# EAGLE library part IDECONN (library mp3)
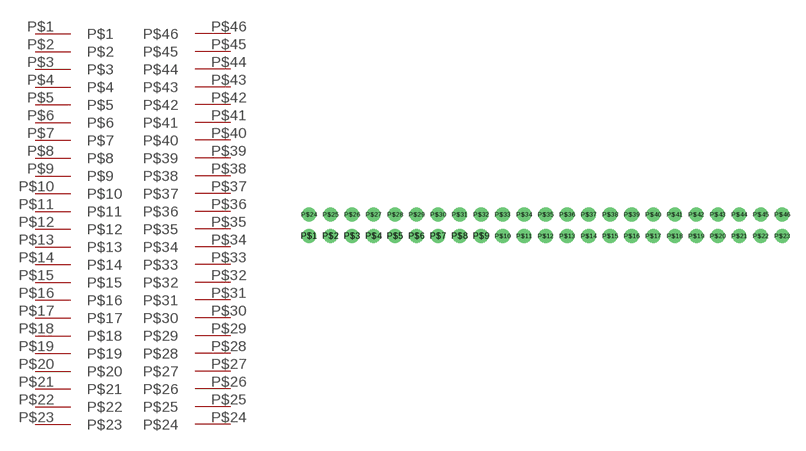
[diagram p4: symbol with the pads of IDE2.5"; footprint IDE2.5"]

Designator prefix -

## IDECONN  [IDE2.5"]
P$1  P$1
P$2  P$2
P$3  P$3
P$4  P$4
P$5  P$5
P$6  P$6
P$7  P$7
P$8  P$8
P$9  P$9
P$10  P$10
P$11  P$11
P$12  P$12
P$13  P$13
P$14  P$14
P$15  P$15
P$16  P$16
P$17  P$17
P$18  P$18
P$19  P$19
P$20  P$20
P$21  P$21
P$22  P$22
P$23  P$23
P$24  P$24
P$25  P$25
P$26  P$26
P$27  P$27
P$28  P$28
P$29  P$29
P$30  P$30
P$31  P$31
P$32  P$32
P$33  P$33
P$34  P$34
P$35  P$35
P$36  P$36
P$37  P$37
P$38  P$38
P$39  P$39
P$40  P$40
P$41  P$41
P$42  P$42
P$43  P$43
P$44  P$44
P$45  P$45
P$46  P$46

## Footprint IDE2.5" (pad centres in mm)
drill 0.813 round: P$1 -20,0; P$2 -18,0; P$3 -16,0; P$4 -14,0; P$5 -12,0; P$6 -10,0; P$7 -8,0; P$8 -6,0; P$9 -4,0; P$10 -2,0; P$11 0,0; P$12 2,0; P$13 4,0; P$14 6,0; P$15 8,0; P$16 10,0; P$17 12,0; P$18 14,0; P$19 16,0; P$20 18,0; P$21 20,0; P$22 22,0; P$23 24,0; P$24 -20,2; P$25 -18,2; P$26 -16,2; P$27 -14,2; P$28 -12,2; P$29 -10,2; P$30 -8,2; P$31 -6,2; P$32 -4,2; P$33 -2,2; P$34 0,2; P$35 2,2; P$36 4,2; P$37 6,2; P$38 8,2; P$39 10,2; P$40 12,2; P$41 14,2; P$42 16,2; P$43 18,2; P$44 20,2; P$45 22,2; P$46 24,2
